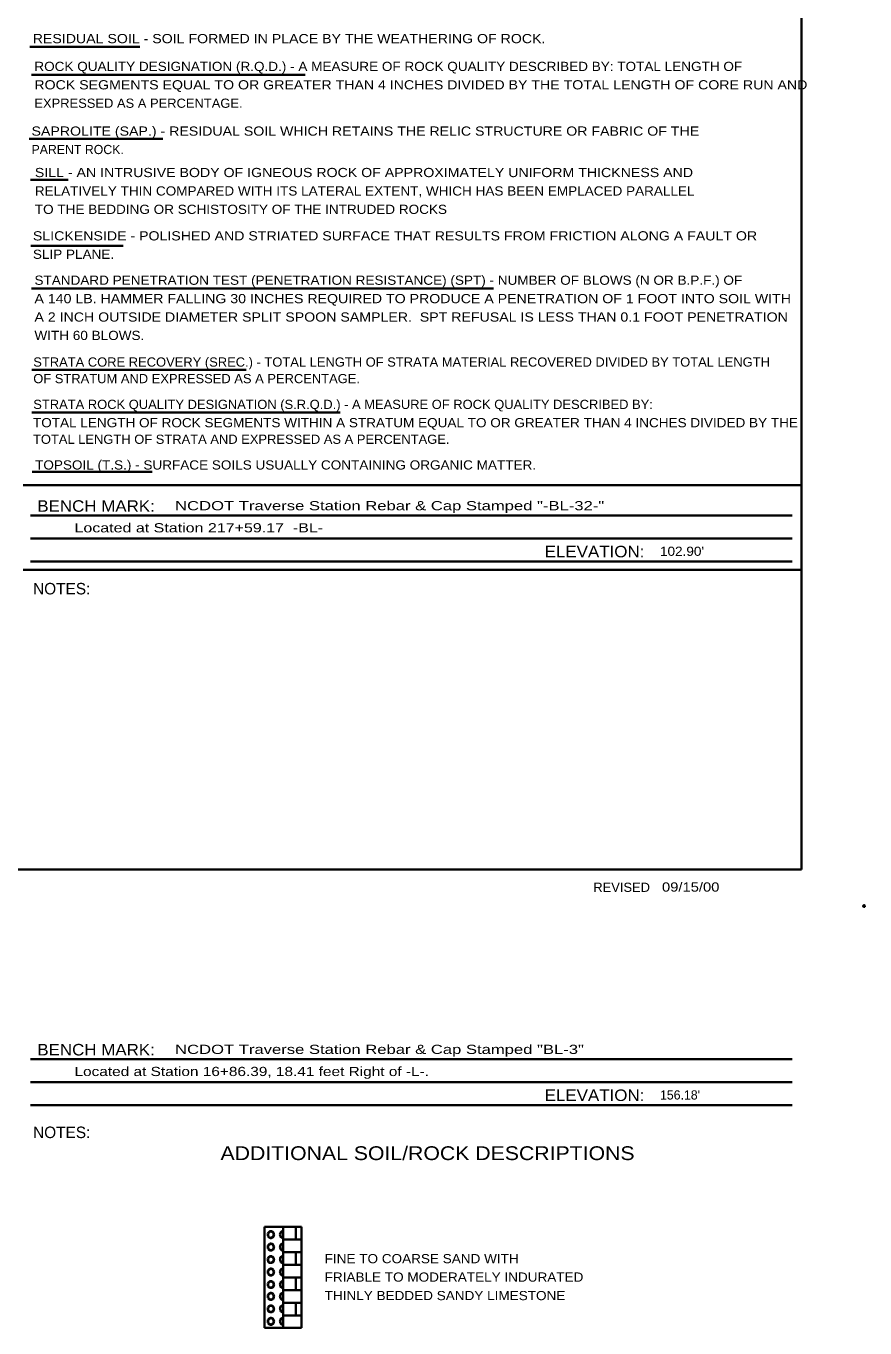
# Model space of a CAD drawing. Extents: x 2137492.6 to 2137529.1, y 2137475.8 to 2137563.
# Drawn here: x 2137519.94 to 2137529.06, y 2137534.75 to 2137548.89 of the extents above; entities that cross this region are included whole.
import ezdxf
from ezdxf.enums import TextEntityAlignment as Align

# ---------------------------------------------------------------- set-up
doc = ezdxf.new("R2010")
doc.units = 0
doc.header["$LTSCALE"] = 0.04
doc.header["$PDMODE"] = 32
doc.header["$PDSIZE"] = 0.02
doc.layers.add('1', color=7, linetype='Continuous', lineweight=35)
doc.layers.add('27', color=7, linetype='Continuous', lineweight=40)

msp = doc.modelspace()

# ---------------------------------------------------------------- linework, layer by layer
at = {"layer": '1'}
for p, q in [((2137528.371, 2137561.718), (2137528.371, 2137539.727)), ((2137528.371, 2137558.425), (2137528.371, 2137539.727)), ((2137519.985, 2137548.666), (2137521.181, 2137548.666)), ((2137520.003, 2137548.359), (2137522.976, 2137548.359)), ((2137519.977, 2137547.665), (2137521.431, 2137547.665)), ((2137519.993, 2137547.219), (2137520.402, 2137547.219)), ((2137519.998, 2137546.504), (2137521, 2137546.504)), ((2137520.003, 2137546.04), (2137525.022, 2137546.04)), ((2137520.008, 2137545.156), (2137522.335, 2137545.156)), ((2137520.006, 2137544.692), (2137523.357, 2137544.692)), ((2137520.011, 2137544.048), (2137521.314, 2137544.048)), ((2137519.912, 2137543.903), (2137528.371, 2137543.903)), ((2137519.994, 2137543.571), (2137528.27, 2137543.571)), ((2137519.994, 2137543.321), (2137528.27, 2137543.321)), ((2137519.912, 2137542.983), (2137528.371, 2137542.983)), ((2137519.994, 2137543.071), (2137528.27, 2137543.071)), ((2137519.994, 2137537.664), (2137528.27, 2137537.664)), ((2137519.994, 2137537.414), (2137528.27, 2137537.414)), ((2137519.994, 2137537.164), (2137528.27, 2137537.164)), ((2137522.537, 2137535.845), (2137522.937, 2137535.845)), ((2137522.537, 2137535.845), (2137522.537, 2137534.745)), ((2137522.737, 2137534.745), (2137522.737, 2137535.845)), ((2137522.875, 2137535.707), (2137522.875, 2137535.845)), ((2137522.937, 2137534.745), (2137522.937, 2137535.845)), ((2137522.737, 2137535.707), (2137522.937, 2137535.707)), ((2137522.737, 2137535.569), (2137522.937, 2137535.569)), ((2137522.875, 2137535.432), (2137522.875, 2137535.569)), ((2137522.737, 2137535.432), (2137522.937, 2137535.432)), ((2137522.737, 2137535.294), (2137522.937, 2137535.294)), ((2137522.875, 2137535.156), (2137522.875, 2137535.294)), ((2137522.737, 2137535.156), (2137522.937, 2137535.156)), ((2137522.737, 2137535.018), (2137522.937, 2137535.018)), ((2137522.875, 2137534.88), (2137522.875, 2137535.018)), ((2137522.737, 2137534.88), (2137522.937, 2137534.88)), ((2137522.537, 2137534.745), (2137522.937, 2137534.745))]:
    msp.add_line(p, q, dxfattribs=at)
msp.add_lwpolyline([(2137493.171, 2137561.718), (2137493.171, 2137539.727), (2137528.371, 2137539.727)], dxfattribs=at)
msp.add_point((2137529.05, 2137539.329), dxfattribs=at)
at = {"layer": '27'}
for points in [[(2137522.639, 2137535.76), (2137522.638, 2137535.765), (2137522.637, 2137535.77), (2137522.635, 2137535.775), (2137522.632, 2137535.78), (2137522.629, 2137535.784), (2137522.625, 2137535.787), (2137522.62, 2137535.79), (2137522.615, 2137535.792), (2137522.61, 2137535.793), (2137522.605, 2137535.794), (2137522.6, 2137535.793), (2137522.595, 2137535.792), (2137522.59, 2137535.79), (2137522.585, 2137535.787), (2137522.581, 2137535.784), (2137522.578, 2137535.78), (2137522.575, 2137535.776), (2137522.573, 2137535.771), (2137522.571, 2137535.766), (2137522.571, 2137535.76), (2137522.571, 2137535.755), (2137522.572, 2137535.75), (2137522.574, 2137535.745), (2137522.577, 2137535.74), (2137522.58, 2137535.736), (2137522.584, 2137535.733), (2137522.589, 2137535.73), (2137522.593, 2137535.728), (2137522.599, 2137535.726), (2137522.604, 2137535.726), (2137522.609, 2137535.726), (2137522.614, 2137535.727), (2137522.619, 2137535.729), (2137522.624, 2137535.732), (2137522.628, 2137535.735), (2137522.632, 2137535.739), (2137522.634, 2137535.743), (2137522.637, 2137535.748), (2137522.638, 2137535.753), (2137522.639, 2137535.759)], [(2137522.639, 2137535.624), (2137522.638, 2137535.629), (2137522.637, 2137535.634), (2137522.635, 2137535.639), (2137522.632, 2137535.644), (2137522.629, 2137535.648), (2137522.625, 2137535.651), (2137522.62, 2137535.654), (2137522.615, 2137535.656), (2137522.61, 2137535.657), (2137522.605, 2137535.658), (2137522.6, 2137535.658), (2137522.595, 2137535.656), (2137522.59, 2137535.654), (2137522.585, 2137535.652), (2137522.581, 2137535.648), (2137522.578, 2137535.644), (2137522.575, 2137535.64), (2137522.573, 2137535.635), (2137522.571, 2137535.63), (2137522.571, 2137535.625), (2137522.571, 2137535.619), (2137522.572, 2137535.614), (2137522.574, 2137535.609), (2137522.577, 2137535.605), (2137522.58, 2137535.6), (2137522.584, 2137535.597), (2137522.589, 2137535.594), (2137522.593, 2137535.592), (2137522.599, 2137535.591), (2137522.604, 2137535.59), (2137522.609, 2137535.59), (2137522.614, 2137535.591), (2137522.619, 2137535.593), (2137522.624, 2137535.596), (2137522.628, 2137535.599), (2137522.632, 2137535.603), (2137522.634, 2137535.608), (2137522.637, 2137535.612), (2137522.638, 2137535.618), (2137522.639, 2137535.623)], [(2137522.639, 2137535.488), (2137522.638, 2137535.494), (2137522.637, 2137535.499), (2137522.635, 2137535.504), (2137522.632, 2137535.508), (2137522.629, 2137535.512), (2137522.625, 2137535.516), (2137522.62, 2137535.518), (2137522.615, 2137535.52), (2137522.61, 2137535.522), (2137522.605, 2137535.522), (2137522.6, 2137535.522), (2137522.595, 2137535.521), (2137522.59, 2137535.519), (2137522.585, 2137535.516), (2137522.581, 2137535.513), (2137522.578, 2137535.509), (2137522.575, 2137535.504), (2137522.573, 2137535.499), (2137522.571, 2137535.494), (2137522.571, 2137535.489), (2137522.571, 2137535.484), (2137522.572, 2137535.478), (2137522.574, 2137535.473), (2137522.577, 2137535.469), (2137522.58, 2137535.465), (2137522.584, 2137535.461), (2137522.589, 2137535.458), (2137522.593, 2137535.456), (2137522.599, 2137535.455), (2137522.604, 2137535.454), (2137522.609, 2137535.455), (2137522.614, 2137535.456), (2137522.619, 2137535.458), (2137522.624, 2137535.46), (2137522.628, 2137535.463), (2137522.632, 2137535.467), (2137522.634, 2137535.472), (2137522.637, 2137535.477), (2137522.638, 2137535.482), (2137522.639, 2137535.487)], [(2137522.639, 2137535.352), (2137522.638, 2137535.358), (2137522.637, 2137535.363), (2137522.635, 2137535.368), (2137522.632, 2137535.372), (2137522.629, 2137535.376), (2137522.625, 2137535.38), (2137522.62, 2137535.383), (2137522.615, 2137535.385), (2137522.61, 2137535.386), (2137522.605, 2137535.386), (2137522.6, 2137535.386), (2137522.595, 2137535.385), (2137522.59, 2137535.383), (2137522.585, 2137535.38), (2137522.581, 2137535.377), (2137522.578, 2137535.373), (2137522.575, 2137535.368), (2137522.573, 2137535.363), (2137522.571, 2137535.358), (2137522.571, 2137535.353), (2137522.571, 2137535.348), (2137522.572, 2137535.343), (2137522.574, 2137535.338), (2137522.577, 2137535.333), (2137522.58, 2137535.329), (2137522.584, 2137535.325), (2137522.589, 2137535.323), (2137522.593, 2137535.32), (2137522.599, 2137535.319), (2137522.604, 2137535.319), (2137522.609, 2137535.319), (2137522.614, 2137535.32), (2137522.619, 2137535.322), (2137522.624, 2137535.324), (2137522.628, 2137535.328), (2137522.632, 2137535.332), (2137522.634, 2137535.336), (2137522.637, 2137535.341), (2137522.638, 2137535.346), (2137522.639, 2137535.351)], [(2137522.639, 2137535.217), (2137522.638, 2137535.222), (2137522.637, 2137535.227), (2137522.635, 2137535.232), (2137522.632, 2137535.237), (2137522.629, 2137535.241), (2137522.625, 2137535.244), (2137522.62, 2137535.247), (2137522.615, 2137535.249), (2137522.61, 2137535.25), (2137522.605, 2137535.251), (2137522.6, 2137535.25), (2137522.595, 2137535.249), (2137522.59, 2137535.247), (2137522.585, 2137535.244), (2137522.581, 2137535.241), (2137522.578, 2137535.237), (2137522.575, 2137535.233), (2137522.573, 2137535.228), (2137522.571, 2137535.223), (2137522.571, 2137535.217), (2137522.571, 2137535.212), (2137522.572, 2137535.207), (2137522.574, 2137535.202), (2137522.577, 2137535.197), (2137522.58, 2137535.193), (2137522.584, 2137535.19), (2137522.589, 2137535.187), (2137522.593, 2137535.185), (2137522.599, 2137535.183), (2137522.604, 2137535.183), (2137522.609, 2137535.183), (2137522.614, 2137535.184), (2137522.619, 2137535.186), (2137522.624, 2137535.189), (2137522.628, 2137535.192), (2137522.632, 2137535.196), (2137522.634, 2137535.2), (2137522.637, 2137535.205), (2137522.638, 2137535.21), (2137522.639, 2137535.216)], [(2137522.639, 2137535.088), (2137522.638, 2137535.094), (2137522.637, 2137535.099), (2137522.635, 2137535.104), (2137522.632, 2137535.108), (2137522.629, 2137535.112), (2137522.625, 2137535.116), (2137522.62, 2137535.118), (2137522.615, 2137535.12), (2137522.61, 2137535.122), (2137522.605, 2137535.122), (2137522.6, 2137535.122), (2137522.595, 2137535.121), (2137522.59, 2137535.119), (2137522.585, 2137535.116), (2137522.581, 2137535.113), (2137522.578, 2137535.109), (2137522.575, 2137535.104), (2137522.573, 2137535.099), (2137522.571, 2137535.094), (2137522.571, 2137535.089), (2137522.571, 2137535.084), (2137522.572, 2137535.078), (2137522.574, 2137535.073), (2137522.577, 2137535.069), (2137522.58, 2137535.065), (2137522.584, 2137535.061), (2137522.589, 2137535.058), (2137522.593, 2137535.056), (2137522.599, 2137535.055), (2137522.604, 2137535.054), (2137522.609, 2137535.055), (2137522.614, 2137535.056), (2137522.619, 2137535.058), (2137522.624, 2137535.06), (2137522.628, 2137535.063), (2137522.632, 2137535.067), (2137522.634, 2137535.072), (2137522.637, 2137535.077), (2137522.638, 2137535.082), (2137522.639, 2137535.087)], [(2137522.639, 2137534.952), (2137522.638, 2137534.958), (2137522.637, 2137534.963), (2137522.635, 2137534.968), (2137522.632, 2137534.972), (2137522.629, 2137534.976), (2137522.625, 2137534.98), (2137522.62, 2137534.983), (2137522.615, 2137534.985), (2137522.61, 2137534.986), (2137522.605, 2137534.986), (2137522.6, 2137534.986), (2137522.595, 2137534.985), (2137522.59, 2137534.983), (2137522.585, 2137534.98), (2137522.581, 2137534.977), (2137522.578, 2137534.973), (2137522.575, 2137534.968), (2137522.573, 2137534.963), (2137522.571, 2137534.958), (2137522.571, 2137534.953), (2137522.571, 2137534.948), (2137522.572, 2137534.943), (2137522.574, 2137534.938), (2137522.577, 2137534.933), (2137522.58, 2137534.929), (2137522.584, 2137534.925), (2137522.589, 2137534.923), (2137522.593, 2137534.92), (2137522.599, 2137534.919), (2137522.604, 2137534.919), (2137522.609, 2137534.919), (2137522.614, 2137534.92), (2137522.619, 2137534.922), (2137522.624, 2137534.924), (2137522.628, 2137534.928), (2137522.632, 2137534.932), (2137522.634, 2137534.936), (2137522.637, 2137534.941), (2137522.638, 2137534.946), (2137522.639, 2137534.951)], [(2137522.639, 2137534.817), (2137522.638, 2137534.822), (2137522.637, 2137534.827), (2137522.635, 2137534.832), (2137522.632, 2137534.837), (2137522.629, 2137534.841), (2137522.625, 2137534.844), (2137522.62, 2137534.847), (2137522.615, 2137534.849), (2137522.61, 2137534.85), (2137522.605, 2137534.851), (2137522.6, 2137534.85), (2137522.595, 2137534.849), (2137522.59, 2137534.847), (2137522.585, 2137534.844), (2137522.581, 2137534.841), (2137522.578, 2137534.837), (2137522.575, 2137534.833), (2137522.573, 2137534.828), (2137522.571, 2137534.823), (2137522.571, 2137534.817), (2137522.571, 2137534.812), (2137522.572, 2137534.807), (2137522.574, 2137534.802), (2137522.577, 2137534.797), (2137522.58, 2137534.793), (2137522.584, 2137534.79), (2137522.589, 2137534.787), (2137522.593, 2137534.785), (2137522.599, 2137534.783), (2137522.604, 2137534.783), (2137522.609, 2137534.783), (2137522.614, 2137534.784), (2137522.619, 2137534.786), (2137522.624, 2137534.789), (2137522.628, 2137534.792), (2137522.632, 2137534.796), (2137522.634, 2137534.8), (2137522.637, 2137534.805), (2137522.638, 2137534.81), (2137522.639, 2137534.816)]]:
    msp.add_lwpolyline(points, close=True, dxfattribs=at)
for points in [[(2137522.737, 2137535.794), (2137522.732, 2137535.793), (2137522.727, 2137535.792), (2137522.722, 2137535.79), (2137522.718, 2137535.787), (2137522.713, 2137535.784), (2137522.71, 2137535.78), (2137522.707, 2137535.776), (2137522.705, 2137535.771), (2137522.704, 2137535.766), (2137522.703, 2137535.76), (2137522.704, 2137535.755), (2137522.705, 2137535.75), (2137522.707, 2137535.745), (2137522.709, 2137535.74), (2137522.713, 2137535.736), (2137522.717, 2137535.733), (2137522.721, 2137535.73), (2137522.726, 2137535.728), (2137522.731, 2137535.726), (2137522.736, 2137535.726), (2137522.737, 2137535.726)], [(2137522.737, 2137535.658), (2137522.732, 2137535.658), (2137522.727, 2137535.656), (2137522.722, 2137535.654), (2137522.718, 2137535.652), (2137522.713, 2137535.648), (2137522.71, 2137535.644), (2137522.707, 2137535.64), (2137522.705, 2137535.635), (2137522.704, 2137535.63), (2137522.703, 2137535.625), (2137522.704, 2137535.619), (2137522.705, 2137535.614), (2137522.707, 2137535.609), (2137522.709, 2137535.605), (2137522.713, 2137535.6), (2137522.717, 2137535.597), (2137522.721, 2137535.594), (2137522.726, 2137535.592), (2137522.731, 2137535.591), (2137522.736, 2137535.59), (2137522.737, 2137535.59)], [(2137522.737, 2137535.522), (2137522.732, 2137535.522), (2137522.727, 2137535.521), (2137522.722, 2137535.519), (2137522.718, 2137535.516), (2137522.713, 2137535.513), (2137522.71, 2137535.509), (2137522.707, 2137535.504), (2137522.705, 2137535.499), (2137522.704, 2137535.494), (2137522.703, 2137535.489), (2137522.704, 2137535.484), (2137522.705, 2137535.478), (2137522.707, 2137535.473), (2137522.709, 2137535.469), (2137522.713, 2137535.465), (2137522.717, 2137535.461), (2137522.721, 2137535.458), (2137522.726, 2137535.456), (2137522.731, 2137535.455), (2137522.736, 2137535.454), (2137522.737, 2137535.454)], [(2137522.737, 2137535.386), (2137522.732, 2137535.386), (2137522.727, 2137535.385), (2137522.722, 2137535.383), (2137522.718, 2137535.38), (2137522.713, 2137535.377), (2137522.71, 2137535.373), (2137522.707, 2137535.368), (2137522.705, 2137535.363), (2137522.704, 2137535.358), (2137522.703, 2137535.353), (2137522.704, 2137535.348), (2137522.705, 2137535.343), (2137522.707, 2137535.338), (2137522.709, 2137535.333), (2137522.713, 2137535.329), (2137522.717, 2137535.325), (2137522.721, 2137535.323), (2137522.726, 2137535.32), (2137522.731, 2137535.319), (2137522.736, 2137535.319), (2137522.737, 2137535.319)], [(2137522.737, 2137535.251), (2137522.732, 2137535.25), (2137522.727, 2137535.249), (2137522.722, 2137535.247), (2137522.718, 2137535.244), (2137522.713, 2137535.241), (2137522.71, 2137535.237), (2137522.707, 2137535.233), (2137522.705, 2137535.228), (2137522.704, 2137535.223), (2137522.703, 2137535.217), (2137522.704, 2137535.212), (2137522.705, 2137535.207), (2137522.707, 2137535.202), (2137522.709, 2137535.197), (2137522.713, 2137535.193), (2137522.717, 2137535.19), (2137522.721, 2137535.187), (2137522.726, 2137535.185), (2137522.731, 2137535.183), (2137522.736, 2137535.183), (2137522.737, 2137535.183)], [(2137522.737, 2137535.122), (2137522.732, 2137535.122), (2137522.727, 2137535.121), (2137522.722, 2137535.119), (2137522.718, 2137535.116), (2137522.713, 2137535.113), (2137522.71, 2137535.109), (2137522.707, 2137535.104), (2137522.705, 2137535.099), (2137522.704, 2137535.094), (2137522.703, 2137535.089), (2137522.704, 2137535.084), (2137522.705, 2137535.078), (2137522.707, 2137535.073), (2137522.709, 2137535.069), (2137522.713, 2137535.065), (2137522.717, 2137535.061), (2137522.721, 2137535.058), (2137522.726, 2137535.056), (2137522.731, 2137535.055), (2137522.736, 2137535.054), (2137522.737, 2137535.054)], [(2137522.737, 2137534.986), (2137522.732, 2137534.986), (2137522.727, 2137534.985), (2137522.722, 2137534.983), (2137522.718, 2137534.98), (2137522.713, 2137534.977), (2137522.71, 2137534.973), (2137522.707, 2137534.968), (2137522.705, 2137534.963), (2137522.704, 2137534.958), (2137522.703, 2137534.953), (2137522.704, 2137534.948), (2137522.705, 2137534.943), (2137522.707, 2137534.938), (2137522.709, 2137534.933), (2137522.713, 2137534.929), (2137522.717, 2137534.925), (2137522.721, 2137534.923), (2137522.726, 2137534.92), (2137522.731, 2137534.919), (2137522.736, 2137534.919), (2137522.737, 2137534.919)], [(2137522.737, 2137534.851), (2137522.732, 2137534.85), (2137522.727, 2137534.849), (2137522.722, 2137534.847), (2137522.718, 2137534.844), (2137522.713, 2137534.841), (2137522.71, 2137534.837), (2137522.707, 2137534.833), (2137522.705, 2137534.828), (2137522.704, 2137534.823), (2137522.703, 2137534.817), (2137522.704, 2137534.812), (2137522.705, 2137534.807), (2137522.707, 2137534.802), (2137522.709, 2137534.797), (2137522.713, 2137534.793), (2137522.717, 2137534.79), (2137522.721, 2137534.787), (2137522.726, 2137534.785), (2137522.731, 2137534.783), (2137522.736, 2137534.783), (2137522.737, 2137534.783)]]:
    msp.add_lwpolyline(points, dxfattribs=at)

# ---------------------------------------------------------------- texts
at = {"layer": '1'}
for s, height, width, p in [('RESIDUAL SOIL - SOIL FORMED IN PLACE BY THE WEATHERING OF ROCK.', 0.1, 1.15, (2137520.017, 2137548.704)), ('ROCK QUALITY DESIGNATION (R.Q.D.) - A MEASURE OF ROCK QUALITY DESCRIBED BY: TOTAL LENGTH OF ', 0.1, 1.1, (2137520.035, 2137548.402)), ('ROCK SEGMENTS EQUAL TO OR GREATER THAN 4 INCHES DIVIDED BY THE TOTAL LENGTH OF CORE RUN AND ', 0.1, 1.15, (2137520.035, 2137548.202)), ('EXPRESSED AS A PERCENTAGE.', 0.1, 1.05, (2137520.035, 2137548.002)), ('SAPROLITE (SAP.) - RESIDUAL SOIL WHICH RETAINS THE RELIC STRUCTURE OR FABRIC OF THE ', 0.1, 1.15, (2137520.004, 2137547.699)), ('SILL - AN INTRUSIVE BODY OF IGNEOUS ROCK OF APPROXIMATELY UNIFORM THICKNESS AND', 0.1, 1.15, (2137520.04, 2137547.249)), ('RELATIVELY THIN COMPARED WITH ITS LATERAL EXTENT, WHICH HAS BEEN EMPLACED PARALLEL', 0.1, 1.1, (2137520.04, 2137547.049)), ('TO THE BEDDING OR SCHISTOSITY OF THE INTRUDED ROCKS', 0.1, 1.1, (2137520.04, 2137546.849)), ('SLICKENSIDE - POLISHED AND STRIATED SURFACE THAT RESULTS FROM FRICTION ALONG A FAULT OR ', 0.1, 1.15, (2137520.019, 2137546.561)), ('SLIP PLANE.', 0.1, 1.1, (2137520.019, 2137546.361)), ('STANDARD PENETRATION TEST (PENETRATION RESISTANCE) (SPT) - NUMBER OF BLOWS (N OR B.P.F.) OF ', 0.1, 1.1, (2137520.036, 2137546.079)), ('A 140 LB. HAMMER FALLING 30 INCHES REQUIRED TO PRODUCE A PENETRATION OF 1 FOOT INTO SOIL WITH ', 0.1, 1.15, (2137520.036, 2137545.879)), ('A 2 INCH OUTSIDE DIAMETER SPLIT SPOON SAMPLER.  SPT REFUSAL IS LESS THAN 0.1 FOOT PENETRATION ', 0.1, 1.15, (2137520.036, 2137545.679)), ('WITH 60 BLOWS.', 0.1, 1.1, (2137520.036, 2137545.479)), ('STRATA CORE RECOVERY (SREC.) - TOTAL LENGTH OF STRATA MATERIAL RECOVERED DIVIDED BY TOTAL LENGTH', 0.1, 1.05, (2137520.023, 2137545.19)), ('OF STRATUM AND EXPRESSED AS A PERCENTAGE.', 0.1, 1.05, (2137520.023, 2137545.01)), ('STRATA ROCK QUALITY DESIGNATION (S.R.Q.D.) - A MEASURE OF ROCK QUALITY DESCRIBED BY:', 0.1, 1.05, (2137520.023, 2137544.73)), ('TOTAL LENGTH OF ROCK SEGMENTS WITHIN A STRATUM EQUAL TO OR GREATER THAN 4 INCHES DIVIDED BY THE', 0.1, 1.1, (2137520.02, 2137544.531)), ('TOTAL LENGTH OF STRATA AND EXPRESSED AS A PERCENTAGE.', 0.1, 1.05, (2137520.02, 2137544.351)), ('TOPSOIL (T.S.) - SURFACE SOILS USUALLY CONTAINING ORGANIC MATTER.', 0.1, 1.1, (2137520.043, 2137544.072)), ('BENCH MARK:', 0.125, 1.1, (2137520.067, 2137543.613)), ('NCDOT Traverse Station Rebar & Cap Stamped "-BL-32-"', 0.1, 1.35, (2137521.564, 2137543.629)), ('Located at Station 217+59.17  -BL-', 0.1, 1.3, (2137520.471, 2137543.389)), ('ELEVATION:', 0.125, 1.1, (2137525.58, 2137543.118)), ("102.90'", 0.1, 1.1, (2137526.833, 2137543.134)), ('REVISED ', 0.1, 1.05, (2137526.108, 2137539.483)), ('09/15/00', 0.1, 1.2, (2137526.854, 2137539.486)), ('BENCH MARK:', 0.125, 1.1, (2137520.067, 2137537.706)), ('NCDOT Traverse Station Rebar & Cap Stamped "BL-3"', 0.1, 1.35, (2137521.564, 2137537.722)), ('Located at Station 16+86.39, 18.41 feet Right of -L-.', 0.1, 1.25, (2137520.471, 2137537.482)), ('ELEVATION:', 0.125, 1.1, (2137525.58, 2137537.211)), ('FINE TO COARSE SAND WITH', 0.1, 1.1, (2137523.189, 2137535.448)), ('FRIABLE TO MODERATELY INDURATED', 0.1, 1.1, (2137523.189, 2137535.248)), ('THINLY BEDDED SANDY LIMESTONE', 0.1, 1.1, (2137523.189, 2137535.047))]:
    msp.add_text(s, height=height, dxfattribs=dict(at, width=width)).set_placement(p)
for s, height, p in [('PARENT ROCK.', 0.1, (2137520.004, 2137547.499)), ('NOTES:', 0.125, (2137520.021, 2137542.715)), ("156.18'", 0.1, (2137526.833, 2137537.227)), ('NOTES:', 0.125, (2137520.021, 2137536.808))]:
    msp.add_text(s, height=height, dxfattribs=at).set_placement(p)
at = {"layer": '1', "width": 1.15}
msp.add_text('ADDITIONAL SOIL/ROCK DESCRIPTIONS', height=0.15, dxfattribs=at).set_placement((2137524.307, 2137536.569), align=Align.CENTER)

doc.saveas('drawing.dxf')
